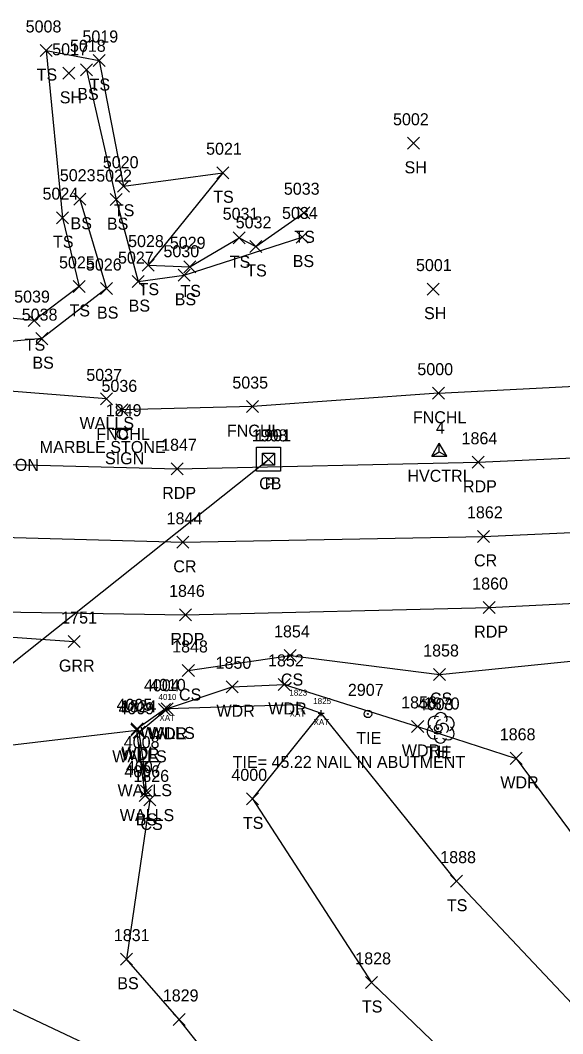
# Model space of a CAD drawing. Extents: x 1509053 to 1511576, y 400838 to 402572.
# Drawn here: x 1510394.2 to 1510484.5, y 401567.3 to 401736 of the extents above; entities that cross this region are included whole.
import ezdxf

# ---------------------------------------------------------------- set-up
doc = ezdxf.new("R2010")
doc.units = 0
for name, color, linetype in [('B_A', 7, 'Continuous'), ('B_I', 7, 'Continuous'), ('B_TIC', 7, 'Continuous'), ('BSUBM', 7, 'Continuous'), ('C_A', 7, 'Continuous'), ('C_C', 7, 'Continuous'), ('C_I', 7, 'Continuous'), ('CBP', 7, 'Continuous'), ('CPSM', 7, 'Continuous'), ('D_A', 7, 'Continuous'), ('D_I', 7, 'Continuous'), ('D_TIC', 7, 'Continuous'), ('DCP', 7, 'Continuous'), ('DS', 7, 'Continuous'), ('L_A', 7, 'Continuous'), ('L_C', 7, 'Continuous'), ('L_I', 7, 'Continuous'), ('L_TIC', 7, 'Continuous'), ('LAWA', 7, 'Continuous'), ('LELB', 7, 'Continuous'), ('LFNC', 7, 'Continuous'), ('LTD', 7, 'Continuous'), ('LWS', 7, 'Continuous'), ('P_A', 7, 'Continuous'), ('P_I', 7, 'Continuous'), ('P_TIC', 7, 'Continuous'), ('PET', 7, 'Continuous'), ('PRC', 7, 'Continuous'), ('R_A', 7, 'Continuous'), ('R_I', 7, 'Continuous'), ('R_TIC', 7, 'Continuous'), ('RGR', 7, 'Continuous'), ('S_A', 7, 'Continuous'), ('S_I', 7, 'Continuous'), ('SSGN', 7, 'Continuous')]:
    doc.layers.add(name, color=color, linetype=linetype)

msp = doc.modelspace()

# ---------------------------------------------------------------- linework, layer by layer
at = {"layer": 'B_TIC'}
for p, q in [((1510440.36, 401622.08), (1510440.44, 401622.08)), ((1510440.36, 401622.08), (1510440.44, 401622.08)), ((1510418.66, 401621.37), (1510418.74, 401621.37)), ((1510444.33, 401620.68), (1510444.41, 401620.68))]:
    msp.add_line(p, q, dxfattribs=at)
for points in [[(1510418.66, 401620.87), (1510418.66, 401621.87)], [(1510439.86, 401622.08), (1510440.86, 401622.08)], [(1510439.86, 401622.08), (1510440.86, 401622.08)], [(1510440.36, 401621.57), (1510440.36, 401622.58)], [(1510440.36, 401621.57), (1510440.36, 401622.58)], [(1510418.16, 401621.37), (1510419.16, 401621.37)], [(1510443.83, 401620.68), (1510444.83, 401620.68)], [(1510444.33, 401620.18), (1510444.33, 401621.18)]]:
    msp.add_lwpolyline(points, dxfattribs=at)
at = {"layer": 'BSUBM'}
for points in [[(1510440.36, 401622.08), (1510418.66, 401621.37)], [(1510440.36, 401622.08), (1510444.33, 401620.68)]]:
    msp.add_lwpolyline(points, dxfattribs=at)
at = {"layer": 'CBP'}
for centre, radius in [((1510452.1, 401620.55), 0.625), ((1510452.1, 401620.55), 0.0833), ((1510463.81, 401618.16), 0.625), ((1510463.81, 401618.16), 0.0833)]:
    msp.add_circle(centre, radius, dxfattribs=at)
at = {"layer": 'CPSM'}
for p, q in [((1510462.73, 401663.46), (1510463.98, 401665.62)), ((1510465.23, 401663.46), (1510463.98, 401665.62)), ((1510463.98, 401664.18), (1510463.98, 401665.62)), ((1510462.73, 401663.46), (1510463.98, 401664.18)), ((1510463.98, 401664.18), (1510463.98, 401664.18)), ((1510463.98, 401664.18), (1510465.23, 401663.46)), ((1510462.73, 401663.46), (1510465.23, 401663.46))]:
    msp.add_line(p, q, dxfattribs=at)
at = {"layer": 'D_TIC'}
for points in [[(1510434.52, 401661.9), (1510436.52, 401663.9)], [(1510436.52, 401661.9), (1510434.52, 401663.9)]]:
    msp.add_lwpolyline(points, dxfattribs=at)
at = {"layer": 'DCP'}
msp.add_lwpolyline([(1510342.37, 401588.83), (1510435.52, 401662.91)], dxfattribs=at)
at = {"layer": 'DS'}
for p, q in [((1510433.54, 401664.93), (1510437.54, 401664.93)), ((1510433.54, 401660.93), (1510433.54, 401664.93)), ((1510434.54, 401661.93), (1510434.54, 401663.93)), ((1510434.54, 401663.93), (1510436.54, 401663.93)), ((1510436.54, 401663.93), (1510436.54, 401661.93)), ((1510437.54, 401664.93), (1510437.54, 401660.93)), ((1510435.54, 401662.93), (1510435.54, 401662.93)), ((1510435.54, 401662.93), (1510435.54, 401662.93)), ((1510437.54, 401660.93), (1510433.54, 401660.93)), ((1510436.54, 401661.93), (1510434.54, 401661.93))]:
    msp.add_line(p, q, dxfattribs=at)
at = {"layer": 'L_TIC'}
for points in [[(1510397.52, 401729.98), (1510399.52, 401731.98)], [(1510399.52, 401729.98), (1510397.52, 401731.98)], [(1510397.52, 401729.98), (1510399.52, 401731.98)], [(1510399.52, 401729.98), (1510397.52, 401731.98)], [(1510406.34, 401728.31), (1510408.34, 401730.31)], [(1510408.34, 401728.31), (1510406.34, 401730.31)], [(1510401.29, 401726.18), (1510403.29, 401728.18)], [(1510403.29, 401726.18), (1510401.29, 401728.18)], [(1510404.25, 401726.76), (1510406.25, 401728.76)], [(1510406.25, 401726.76), (1510404.25, 401728.76)], [(1510458.7, 401714.53), (1510460.7, 401716.53)], [(1510460.7, 401714.53), (1510458.7, 401716.53)], [(1510426.92, 401709.63), (1510428.92, 401711.63)], [(1510428.92, 401709.63), (1510426.92, 401711.63)], [(1510410.38, 401707.38), (1510412.38, 401709.38)], [(1510412.38, 401707.38), (1510410.38, 401709.38)], [(1510403.13, 401705.22), (1510405.13, 401707.22)], [(1510405.13, 401705.22), (1510403.13, 401707.22)], [(1510409.19, 401705.15), (1510411.19, 401707.15)], [(1510411.19, 401705.15), (1510409.19, 401707.15)], [(1510440.44, 401702.97), (1510442.44, 401704.97)], [(1510442.44, 401702.97), (1510440.44, 401704.97)], [(1510400.25, 401702.15), (1510402.25, 401704.15)], [(1510402.25, 401702.15), (1510400.25, 401704.15)], [(1510440.13, 401698.93), (1510442.13, 401700.93)], [(1510442.13, 401698.93), (1510440.13, 401700.93)], [(1510429.68, 401698.81), (1510431.68, 401700.81)], [(1510431.68, 401698.81), (1510429.68, 401700.81)], [(1510432.42, 401697.37), (1510434.42, 401699.37)], [(1510434.42, 401697.37), (1510432.42, 401699.37)], [(1510414.5, 401694.25), (1510416.5, 401696.25)], [(1510416.5, 401694.25), (1510414.5, 401696.25)], [(1510421.46, 401693.97), (1510423.46, 401695.97)], [(1510423.46, 401693.97), (1510421.46, 401695.97)], [(1510420.48, 401692.57), (1510422.48, 401694.57)], [(1510422.48, 401692.57), (1510420.48, 401694.57)], [(1510402.99, 401690.71), (1510404.99, 401692.71)], [(1510404.99, 401690.71), (1510402.99, 401692.71)], [(1510412.81, 401691.51), (1510414.81, 401693.51)], [(1510414.81, 401691.51), (1510412.81, 401693.51)], [(1510407.54, 401690.35), (1510409.54, 401692.35)], [(1510409.54, 401690.35), (1510407.54, 401692.35)], [(1510461.95, 401690.26), (1510463.95, 401692.26)], [(1510463.95, 401690.26), (1510461.95, 401692.26)], [(1510395.54, 401685.01), (1510397.54, 401687.01)], [(1510397.54, 401685.01), (1510395.54, 401687.01)], [(1510396.79, 401682.01), (1510398.79, 401684.01)], [(1510398.79, 401682.01), (1510396.79, 401684.01)], [(1510407.54, 401671.98), (1510409.54, 401673.98)], [(1510409.54, 401671.98), (1510407.54, 401673.98)], [(1510462.83, 401672.93), (1510464.83, 401674.93)], [(1510464.83, 401672.93), (1510462.83, 401674.93)], [(1510431.86, 401670.7), (1510433.86, 401672.7)], [(1510433.86, 401670.7), (1510431.86, 401672.7)], [(1510410.12, 401670.15), (1510412.12, 401672.15)], [(1510412.12, 401670.15), (1510410.12, 401672.15)], [(1510438.16, 401629.27), (1510440.16, 401631.27)], [(1510440.16, 401629.27), (1510438.16, 401631.27)], [(1510421.19, 401626.77), (1510423.19, 401628.77)], [(1510423.19, 401626.77), (1510421.19, 401628.77)], [(1510462.99, 401626.1), (1510464.99, 401628.1)], [(1510464.99, 401626.1), (1510462.99, 401628.1)], [(1510428.51, 401624.06), (1510430.51, 401626.06)], [(1510430.51, 401624.06), (1510428.51, 401626.06)], [(1510437.15, 401624.45), (1510439.15, 401626.45)], [(1510439.15, 401624.45), (1510437.15, 401626.45)], [(1510417.22, 401620.3), (1510419.22, 401622.3)], [(1510419.22, 401620.3), (1510417.22, 401622.3)], [(1510417.22, 401620.3), (1510419.22, 401622.3)], [(1510419.22, 401620.3), (1510417.22, 401622.3)], [(1510417.66, 401620.37), (1510419.66, 401622.37)], [(1510419.66, 401620.37), (1510417.66, 401622.37)], [(1510412.62, 401616.82), (1510414.62, 401618.82)], [(1510414.62, 401616.82), (1510412.62, 401618.82)], [(1510412.66, 401617.07), (1510414.66, 401619.07)], [(1510414.66, 401617.07), (1510412.66, 401619.07)], [(1510412.98, 401616.48), (1510414.98, 401618.48)], [(1510414.98, 401616.48), (1510412.98, 401618.48)], [(1510459.38, 401617.46), (1510461.38, 401619.46)], [(1510461.38, 401617.46), (1510459.38, 401619.46)], [(1510475.79, 401612.15), (1510477.79, 401614.15)], [(1510477.79, 401612.15), (1510475.79, 401614.15)], [(1510413.86, 401610.85), (1510415.86, 401612.85)], [(1510415.86, 401610.85), (1510413.86, 401612.85)], [(1510414.23, 401606.7), (1510416.23, 401608.7)], [(1510416.23, 401606.7), (1510414.23, 401608.7)], [(1510414.01, 401605.99), (1510416.01, 401607.99)], [(1510416.01, 401605.99), (1510414.01, 401607.99)], [(1510414.78, 401605.23), (1510416.78, 401607.23)], [(1510416.78, 401605.23), (1510414.78, 401607.23)], [(1510431.86, 401605.41), (1510433.86, 401607.41)], [(1510433.86, 401605.41), (1510431.86, 401607.41)], [(1510465.83, 401591.69), (1510467.83, 401593.69)], [(1510467.83, 401591.69), (1510465.83, 401593.69)], [(1510410.92, 401578.72), (1510412.92, 401580.72)], [(1510412.92, 401578.72), (1510410.92, 401580.72)], [(1510451.68, 401574.84), (1510453.68, 401576.84)], [(1510453.68, 401574.84), (1510451.68, 401576.84)], [(1510419.64, 401568.68), (1510421.64, 401570.68)], [(1510421.64, 401568.68), (1510419.64, 401570.68)]]:
    msp.add_lwpolyline(points, dxfattribs=at)
at = {"layer": 'LAWA'}
for points in [[(1510418.22, 401621.3), (1510429.51, 401625.06)], [(1510429.51, 401625.06), (1510438.15, 401625.45), (1510460.38, 401618.46), (1510476.79, 401613.15), (1510508.3, 401570.59), (1510574.11, 401624.66), (1510596.09, 401621.92), (1510599.04, 401608.01)], [(1510418.22, 401621.3), (1510413.66, 401618.07)], [(1510371.68, 401612.92), (1510413.62, 401617.82)]]:
    msp.add_lwpolyline(points, dxfattribs=at)
at = {"layer": 'LELB'}
for points in [[(1510398.52, 401730.98), (1510401.25, 401703.15), (1510403.99, 401691.71), (1510396.54, 401686.01), (1510387.99, 401686.88)], [(1510398.52, 401730.98), (1510407.34, 401729.31), (1510411.38, 401708.38), (1510427.92, 401710.63), (1510415.5, 401695.25), (1510422.46, 401694.97), (1510430.68, 401699.81), (1510433.42, 401698.37), (1510441.44, 401703.97)], [(1510405.25, 401727.76), (1510410.19, 401706.15), (1510413.81, 401692.51), (1510421.48, 401693.57), (1510441.13, 401699.93)], [(1510404.13, 401706.22), (1510408.54, 401691.35), (1510397.79, 401683.01), (1510391.43, 401682.42), (1510388.19, 401674.58), (1510383.91, 401670.01)], [(1510422.19, 401627.77), (1510439.16, 401630.28), (1510463.99, 401627.1), (1510524.1, 401633.23), (1510574.11, 401624.66)], [(1510432.86, 401606.41), (1510444.33, 401620.68)], [(1510466.83, 401592.69), (1510444.33, 401620.68)], [(1510415.01, 401606.99), (1510413.62, 401617.82)], [(1510432.86, 401606.41), (1510452.68, 401575.84)], [(1510415.78, 401606.23), (1510411.92, 401579.72)], [(1510522.84, 401532), (1510490.69, 401567.42), (1510466.83, 401592.69)], [(1510431.17, 401556.5), (1510420.64, 401569.68), (1510411.92, 401579.72)], [(1510452.68, 401575.84), (1510475.46, 401553.98), (1510510.5, 401519.16)], [(1510445.73, 401541.95), (1510422.98, 401557.12), (1510389.58, 401572.87)]]:
    msp.add_lwpolyline(points, dxfattribs=at)
at = {"layer": 'LFNC'}
for points in [[(1510463.83, 401673.93), (1510519.07, 401676.76)], [(1510463.83, 401673.93), (1510432.86, 401671.7), (1510411.12, 401671.15)]]:
    msp.add_lwpolyline(points, dxfattribs=at)
at = {"layer": 'LTD'}
msp.add_line((1510464.18, 401618.28), (1510464.18, 401618.28), dxfattribs=at)
msp.add_line((1510464.18, 401618.28), (1510464.18, 401618.28), dxfattribs=at)
msp.add_arc((1510464.23, 401619.72), 1.05, 335.5272, 180.9563, dxfattribs=at)
for centre, major_axis, ratio, start_param, end_param in [((1510463.39, 401618.95), (1.21, -0.51), 0.895232, 1.570796, 4.712389), ((1510465.23, 401618.87), (-1.14, -0.48), 0.949671, 1.570796, 4.712389), ((1510463.1, 401617.57), (0.58, -1.04), 0.959034, 3.141593, 6.283185), ((1510463.98, 401618.74), (-0.208, -0.792), 0.645439, 3.141593, 6.283185), ((1510464.69, 401618.12), (-0.5, 0.667), 0.989748, 3.141593, 6.283185), ((1510465.19, 401617.45), (-1.09, 0.79), 0.841452, 1.570796, 4.712389), ((1510464.19, 401616.78), (0.26, 1.06), 0.942809, 1.570796, 4.712389), ((1510463.73, 401617.53), (-0.625, -0.083), 0.423636, 0, 3.141593)]:
    msp.add_ellipse(centre, major_axis=major_axis, ratio=ratio, start_param=start_param, end_param=end_param, dxfattribs=at)
at = {"layer": 'LWS'}
for points in [[(1510408.54, 401672.98), (1510388.19, 401674.58)], [(1510415.23, 401607.7), (1510414.86, 401611.85), (1510413.98, 401617.48), (1510418.66, 401621.37)]]:
    msp.add_lwpolyline(points, dxfattribs=at)
at = {"layer": 'P_TIC'}
for points in [[(1510419.35, 401660.34), (1510421.35, 401662.34)], [(1510421.35, 401660.34), (1510419.35, 401662.34)], [(1510469.43, 401661.43), (1510471.43, 401663.43)], [(1510471.43, 401661.43), (1510469.43, 401663.43)], [(1510470.33, 401649.1), (1510472.33, 401651.1)], [(1510472.33, 401649.1), (1510470.33, 401651.1)], [(1510420.26, 401648.11), (1510422.26, 401650.11)], [(1510422.26, 401648.11), (1510420.26, 401650.11)], [(1510471.3, 401637.25), (1510473.3, 401639.25)], [(1510473.3, 401637.25), (1510471.3, 401639.25)], [(1510420.73, 401636.03), (1510422.73, 401638.03)], [(1510422.73, 401636.03), (1510420.73, 401638.03)]]:
    msp.add_lwpolyline(points, dxfattribs=at)
at = {"layer": 'PET'}
for points in [[(1510068.52, 401654.76), (1510069.7, 401647.38), (1510117.95, 401657.12), (1510168.51, 401664.21), (1510212.05, 401667), (1510220.39, 401667.36), (1510271.44, 401667.79), (1510321.9, 401665.44), (1510371.76, 401662.64), (1510420.35, 401661.34), (1510470.43, 401662.43), (1510520.33, 401664.72), (1510570.63, 401667.06), (1510593.1, 401669.05), (1510621.58, 401670.53), (1510656.11, 401672.66)], [(1510069.7, 401647.38), (1510070.82, 401637.95), (1510072.41, 401628.04), (1510122.3, 401634.81), (1510170.19, 401640.65), (1510220.23, 401643.86), (1510269.72, 401644.29), (1510320.63, 401641.42), (1510370.24, 401637.87), (1510421.73, 401637.03), (1510472.3, 401638.25), (1510523.24, 401640.81), (1510571.7, 401643.53), (1510622.45, 401646.41), (1510672.72, 401649.13), (1510722.86, 401651.91), (1510723.41, 401651.94), (1510773.15, 401654.37), (1510822.4, 401657.74), (1510872.35, 401660.8), (1510922.85, 401663.95), (1510967.23, 401666.49), (1511034, 401670.65), (1511071.49, 401673.22)]]:
    msp.add_lwpolyline(points, dxfattribs=at)
at = {"layer": 'PRC'}
msp.add_lwpolyline([(1510070.82, 401637.95), (1510120.23, 401645.42), (1510169.76, 401652.13), (1510220.07, 401655.52), (1510220.14, 401655.43), (1510270.51, 401655.53), (1510320.84, 401653.34), (1510371.03, 401650.53), (1510421.26, 401649.11), (1510471.33, 401650.1), (1510521.34, 401652.38), (1510571.58, 401655.12), (1510621.67, 401657.75), (1510671.66, 401660.66), (1510722.15, 401663.46), (1510772.15, 401666.42), (1510822.28, 401669.1), (1510872.26, 401671.98), (1510872.29, 401672.01), (1510922.21, 401674.96), (1510971.31, 401678.08), (1511022.51, 401681.61), (1511070.2, 401684.98)], dxfattribs=at)
at = {"layer": 'R_TIC'}
for points in [[(1510402.16, 401631.59), (1510404.16, 401633.59)], [(1510404.16, 401631.59), (1510402.16, 401633.59)]]:
    msp.add_lwpolyline(points, dxfattribs=at)
at = {"layer": 'RGR'}
msp.add_lwpolyline([(1510073.99, 401627.51), (1510122.46, 401632.98), (1510170.64, 401638.74), (1510220.08, 401641.84), (1510269.6, 401641.85), (1510311.11, 401639.49), (1510334.05, 401636.42), (1510370.16, 401634.91), (1510403.15, 401632.59)], dxfattribs=at)
at = {"layer": 'SSGN'}
for p, q in [((1510409.53, 401667.95), (1510412.86, 401667.95)), ((1510411.17, 401667.12), (1510411.17, 401667.12))]:
    msp.add_line(p, q, dxfattribs=at)
msp.add_circle((1510411.17, 401667.12), 0.833, dxfattribs=at)

# ---------------------------------------------------------------- texts
at = {"layer": 'B_A'}
for p in [(1510417.37, 401619.37), (1510439.06, 401620.08), (1510439.06, 401620.08), (1510443.04, 401618.68)]:
    msp.add_text('XAT', height=1, dxfattribs=at).set_placement(p)
at = {"layer": 'B_I'}
for s, p in [('4010', (1510417.23, 401622.87)), ('1823', (1510439.01, 401623.58)), ('1823', (1510439.01, 401623.58)), ('1825', (1510442.98, 401622.18))]:
    msp.add_text(s, height=1, dxfattribs=at).set_placement(p)
at = {"layer": 'C_A'}
for s, p in [('HVCTRL', (1510458.67, 401659.18)), ('TIE', (1510450.17, 401615.55)), ('TIE', (1510461.89, 401613.16))]:
    msp.add_text(s, height=2, dxfattribs=at).set_placement(p)
at = {"layer": 'C_C'}
for s, p in [('TIE= 80.98 PAINT SPOT ON', (1510362.75, 401661)), ('TIE= 45.22 NAIL IN ABUTMENT', (1510429.58, 401611.55))]:
    msp.add_text(s, height=2, dxfattribs=at).set_placement(p)
at = {"layer": 'C_I'}
for s, p in [('4', (1510463.41, 401667.18)), ('2907', (1510448.76, 401623.55)), ('4003', (1510460.39, 401621.16))]:
    msp.add_text(s, height=2, dxfattribs=at).set_placement(p)
at = {"layer": 'D_A'}
for s, p in [('CB', (1510433.98, 401657.93)), ('P', (1510434.9, 401657.91))]:
    msp.add_text(s, height=2, dxfattribs=at).set_placement(p)
at = {"layer": 'D_I'}
for s, p in [('1908', (1510432.75, 401665.91)), ('1901', (1510433.34, 401665.93))]:
    msp.add_text(s, height=2, dxfattribs=at).set_placement(p)
at = {"layer": 'L_A'}
for s, p in [('TS', (1510396.93, 401725.98)), ('TS', (1510396.93, 401725.98)), ('TS', (1510405.75, 401724.31)), ('BS', (1510403.69, 401722.76)), ('SH', (1510400.78, 401722.18)), ('SH', (1510458.19, 401710.53)), ('TS', (1510426.33, 401705.63)), ('TS', (1510409.79, 401703.38)), ('BS', (1510402.57, 401701.22)), ('BS', (1510408.63, 401701.15)), ('TS', (1510439.85, 401698.97)), ('TS', (1510399.66, 401698.15)), ('TS', (1510429.09, 401694.81)), ('BS', (1510439.57, 401694.93)), ('TS', (1510431.83, 401693.37)), ('TS', (1510413.91, 401690.25)), ('TS', (1510420.87, 401689.97)), ('BS', (1510412.25, 401687.51)), ('BS', (1510419.92, 401688.57)), ('TS', (1510402.4, 401686.71)), ('BS', (1510406.98, 401686.35)), ('SH', (1510461.44, 401686.26)), ('TS', (1510394.95, 401681.01)), ('BS', (1510396.23, 401678.01)), ('FNCHL', (1510459.58, 401668.93)), ('WALLS', (1510404.08, 401667.98)), ('FNCHL', (1510406.87, 401666.15)), ('FNCHL', (1510428.61, 401666.7)), ('CS', (1510437.6, 401625.27)), ('CS', (1510420.63, 401622.77)), ('CS', (1510462.43, 401622.1)), ('WDR', (1510426.87, 401620.06)), ('WDR', (1510435.51, 401620.45)), ('WALLS', (1510414.2, 401616.37)), ('WDR', (1510415.58, 401616.3)), ('WDL', (1510415.64, 401616.3)), ('WDL', (1510411.08, 401613.07)), ('WDR', (1510457.74, 401613.46)), ('H', (1510463.62, 401613.28)), ('WALLS', (1510409.52, 401612.48)), ('WDR', (1510410.99, 401612.82)), ('WDR', (1510474.15, 401608.15)), ('WALLS', (1510410.4, 401606.85)), ('WALLS', (1510410.77, 401602.7)), ('BS', (1510413.45, 401601.99)), ('CS', (1510414.22, 401601.23)), ('TS', (1510431.27, 401601.41)), ('TS', (1510465.24, 401587.7)), ('BS', (1510410.36, 401574.72)), ('TS', (1510451.09, 401570.84))]:
    msp.add_text(s, height=2, dxfattribs=at).set_placement(p)
at = {"layer": 'L_C'}
msp.add_text('MARBLE STONE', height=2, dxfattribs=at).set_placement((1510397.45, 401663.98))
at = {"layer": 'L_I'}
for s, p in [('5008', (1510395.1, 401733.98)), ('5008', (1510395.1, 401733.98)), ('5019', (1510404.56, 401732.31)), ('5017', (1510399.52, 401730.18)), ('5018', (1510402.48, 401730.76)), ('5002', (1510456.28, 401718.53)), ('5021', (1510425.15, 401713.63)), ('5020', (1510407.95, 401711.38)), ('5023', (1510400.79, 401709.22)), ('5022', (1510406.85, 401709.15)), ('5024', (1510397.91, 401706.15)), ('5033', (1510438.1, 401706.97)), ('5031', (1510427.91, 401702.81)), ('5034', (1510437.79, 401702.93)), ('5032', (1510430.08, 401701.37)), ('5028', (1510412.16, 401698.25)), ('5029', (1510419.11, 401697.97)), ('5027', (1510410.48, 401695.51)), ('5030', (1510418.05, 401696.57)), ('5025', (1510400.66, 401694.71)), ('5026', (1510405.14, 401694.35)), ('5001', (1510460.1, 401694.26)), ('5039', (1510393.19, 401689.01)), ('5038', (1510394.45, 401686.01)), ('5000', (1510460.33, 401676.93)), ('5037', (1510405.2, 401675.98)), ('5036', (1510407.73, 401674.15)), ('5035', (1510429.52, 401674.7)), ('1854', (1510436.46, 401633.28)), ('1848', (1510419.5, 401630.77)), ('1858', (1510461.3, 401630.1)), ('1850', (1510426.73, 401628.06)), ('1852', (1510435.46, 401628.45)), ('4004', (1510414.8, 401624.3)), ('4004', (1510414.8, 401624.3)), ('4010', (1510415.8, 401624.37)), ('1856', (1510457.63, 401621.46)), ('1870', (1510461.41, 401621.28)), ('4005', (1510410.24, 401621.07)), ('4009', (1510410.56, 401620.48)), ('1824', (1510410.93, 401620.82)), ('4008', (1510411.44, 401614.85)), ('1868', (1510474.05, 401616.15)), ('4006', (1510411.54, 401609.99)), ('4007', (1510411.81, 401610.7)), ('1826', (1510413.04, 401609.23)), ('4000', (1510429.36, 401609.41)), ('1888', (1510464.14, 401595.7)), ('1831', (1510409.79, 401582.72)), ('1828', (1510449.99, 401578.84)), ('1829', (1510417.94, 401572.68))]:
    msp.add_text(s, height=2, dxfattribs=at).set_placement(p)
at = {"layer": 'P_A'}
for s, p in [('RDP', (1510467.92, 401657.43)), ('RDP', (1510417.84, 401656.34)), ('CR', (1510469.76, 401645.1)), ('CR', (1510419.69, 401644.11)), ('RDP', (1510469.79, 401633.25)), ('RDP', (1510419.22, 401632.03))]:
    msp.add_text(s, height=2, dxfattribs=at).set_placement(p)
at = {"layer": 'P_I'}
for s, p in [('1864', (1510467.69, 401665.43)), ('1847', (1510417.66, 401664.34)), ('1844', (1510418.57, 401652.11)), ('1862', (1510468.59, 401653.1)), ('1846', (1510418.98, 401640.03)), ('1860', (1510469.47, 401641.25))]:
    msp.add_text(s, height=2, dxfattribs=at).set_placement(p)
at = {"layer": 'R_A'}
msp.add_text('GRR', height=2, dxfattribs=at).set_placement((1510400.64, 401627.59))
at = {"layer": 'R_I'}
msp.add_text('1751', height=2, dxfattribs=at).set_placement((1510401.03, 401635.59))
at = {"layer": 'S_A'}
msp.add_text('SIGN', height=2, dxfattribs=at).set_placement((1510408.31, 401662.1))
at = {"layer": 'S_I'}
msp.add_text('1849', height=2, dxfattribs=at).set_placement((1510408.45, 401670.1))

doc.saveas('drawing.dxf')
